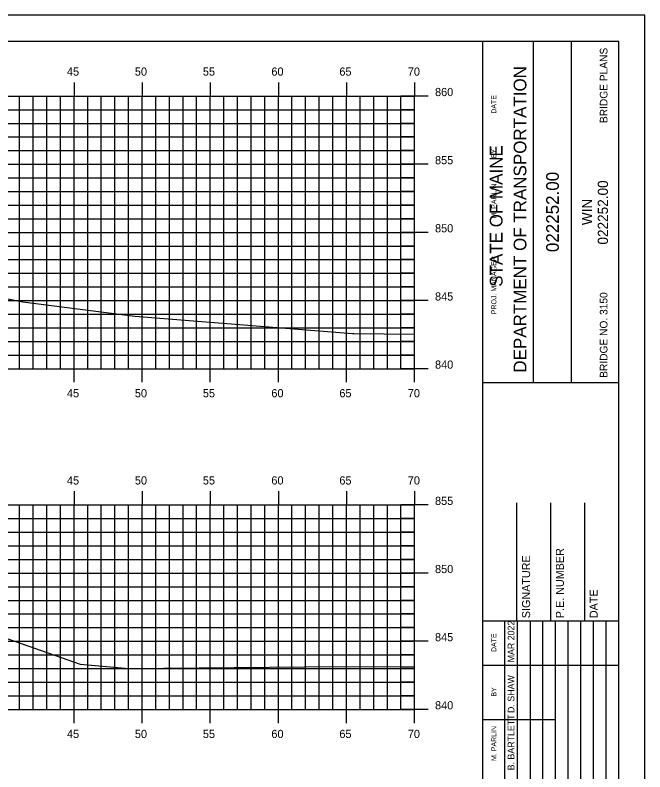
# Model space of a CAD drawing. Extents: x 2194502 to 2194968, y 863888 to 863998.
# Drawn here: x 2194739.2 to 2194785.4, y 863942.9 to 863998.4 of the extents above; entities that cross this region are included whole.
import ezdxf

# ---------------------------------------------------------------- set-up
doc = ezdxf.new("R2010")
doc.units = 0
for name, color, linetype in [('BORDER', 7, 'Continuous'), ('BRIDGE_TITLE', 7, 'Continuous'), ('H_V ANNOTATION', 7, 'Continuous'), ('MAJOR', 7, 'Continuous'), ('MINOR', 7, 'Continuous'), ('PLOT BOUNDARY', 7, 'Continuous'), ('S_Roadway_Centerline', 7, 'Continuous')]:
    doc.layers.add(name, color=color, linetype=linetype)

msp = doc.modelspace()

# ---------------------------------------------------------------- linework, layer by layer
at = {"layer": 'BORDER'}
for p, q in [((2194773.499, 863891.446), (2194773.499, 863996.446)), ((2194777.228, 863971.443), (2194777.228, 863996.443)), ((2194780.023, 863971.443), (2194780.023, 863996.443)), ((2194773.5, 863971.44), (2194783.499, 863971.44)), ((2194775.999, 863953.949), (2194775.999, 863962.596)), ((2194778.499, 863953.949), (2194778.499, 863962.596)), ((2194780.999, 863953.949), (2194780.999, 863962.596)), ((2194773.499, 863953.949), (2194783.499, 863953.949))]:
    msp.add_line(p, q, dxfattribs=at)
msp.add_lwpolyline([(2194623.499, 863891.446), (2194783.499, 863891.446), (2194783.499, 863996.446), (2194623.499, 863996.446)], close=True, dxfattribs=at)
for points in [[(2194775.114, 863950.699), (2194775.114, 863953.949)], [(2194776.047, 863936.452), (2194776.047, 863953.949)], [(2194776.979, 863953.949), (2194776.979, 863936.452)], [(2194777.91, 863936.452), (2194777.91, 863953.949)], [(2194778.842, 863936.452), (2194778.842, 863953.949)], [(2194779.774, 863936.452), (2194779.774, 863953.949)], [(2194780.705, 863936.452), (2194780.705, 863953.949)], [(2194781.637, 863936.452), (2194781.637, 863953.949)], [(2194782.569, 863936.452), (2194782.569, 863953.949)], [(2194775.115, 863936.452), (2194775.115, 863953.243)], [(2194773.499, 863950.699), (2194783.499, 863950.699)], [(2194773.499, 863946.699), (2194775.115, 863946.699)], [(2194775.114, 863946.699), (2194778.841, 863946.699)]]:
    msp.add_lwpolyline(points, dxfattribs=at)
at = {"layer": 'MAJOR'}
for p, q in [((2194743.499, 863993.448), (2194743.499, 863992.446)), ((2194748.499, 863993.448), (2194748.499, 863992.446)), ((2194753.499, 863993.448), (2194753.499, 863992.446)), ((2194758.499, 863993.448), (2194758.499, 863992.446)), ((2194763.499, 863993.448), (2194763.499, 863992.446)), ((2194768.499, 863993.448), (2194768.499, 863992.446)), ((2194628.499, 863992.446), (2194768.499, 863992.446)), ((2194628.499, 863992.446), (2194768.499, 863992.446)), ((2194743.499, 863972.446), (2194743.499, 863992.446)), ((2194748.499, 863972.446), (2194748.499, 863992.446)), ((2194753.499, 863972.446), (2194753.499, 863992.446)), ((2194758.499, 863972.446), (2194758.499, 863992.446)), ((2194763.499, 863972.446), (2194763.499, 863992.446)), ((2194769.501, 863992.446), (2194767.497, 863992.446)), ((2194768.499, 863972.446), (2194768.499, 863992.446)), ((2194768.499, 863972.446), (2194768.499, 863992.446)), ((2194628.499, 863987.446), (2194768.499, 863987.446)), ((2194769.501, 863987.446), (2194767.497, 863987.446)), ((2194628.499, 863982.446), (2194768.499, 863982.446)), ((2194769.501, 863982.446), (2194767.497, 863982.446)), ((2194628.499, 863977.446), (2194768.499, 863977.446)), ((2194769.501, 863977.446), (2194767.497, 863977.446)), ((2194628.499, 863972.446), (2194768.499, 863972.446)), ((2194743.499, 863971.444), (2194743.499, 863972.446)), ((2194748.499, 863971.444), (2194748.499, 863972.446)), ((2194753.499, 863971.444), (2194753.499, 863972.446)), ((2194758.499, 863971.444), (2194758.499, 863972.446)), ((2194763.499, 863971.444), (2194763.499, 863972.446)), ((2194769.501, 863972.446), (2194767.497, 863972.446)), ((2194768.499, 863971.444), (2194768.499, 863972.446)), ((2194743.499, 863963.448), (2194743.499, 863962.446)), ((2194748.499, 863963.448), (2194748.499, 863962.446)), ((2194753.499, 863963.448), (2194753.499, 863962.446)), ((2194758.499, 863963.448), (2194758.499, 863962.446)), ((2194763.499, 863963.448), (2194763.499, 863962.446)), ((2194768.499, 863963.448), (2194768.499, 863962.446)), ((2194628.499, 863962.446), (2194768.499, 863962.446)), ((2194743.499, 863947.446), (2194743.499, 863962.446)), ((2194748.499, 863947.446), (2194748.499, 863962.446)), ((2194753.499, 863947.446), (2194753.499, 863962.446)), ((2194758.499, 863947.446), (2194758.499, 863962.446)), ((2194763.499, 863947.446), (2194763.499, 863962.446)), ((2194769.501, 863962.446), (2194767.497, 863962.446)), ((2194768.499, 863947.446), (2194768.499, 863962.446)), ((2194768.499, 863947.446), (2194768.499, 863962.446)), ((2194628.499, 863957.446), (2194768.499, 863957.446)), ((2194769.501, 863957.446), (2194767.497, 863957.446)), ((2194628.499, 863952.446), (2194768.499, 863952.446)), ((2194769.501, 863952.446), (2194767.497, 863952.446)), ((2194628.499, 863947.446), (2194768.499, 863947.446)), ((2194743.499, 863946.444), (2194743.499, 863947.446)), ((2194748.499, 863946.444), (2194748.499, 863947.446)), ((2194753.499, 863946.444), (2194753.499, 863947.446)), ((2194758.499, 863946.444), (2194758.499, 863947.446)), ((2194763.499, 863946.444), (2194763.499, 863947.446)), ((2194769.501, 863947.446), (2194767.497, 863947.446)), ((2194768.499, 863946.444), (2194768.499, 863947.446))]:
    msp.add_line(p, q, dxfattribs=at)
at = {"layer": 'MINOR'}
for p, q in [((2194739.499, 863972.446), (2194739.499, 863992.446)), ((2194740.499, 863972.446), (2194740.499, 863992.446)), ((2194741.499, 863972.446), (2194741.499, 863992.446)), ((2194742.499, 863972.446), (2194742.499, 863992.446)), ((2194744.499, 863972.446), (2194744.499, 863992.446)), ((2194745.499, 863972.446), (2194745.499, 863992.446)), ((2194746.499, 863972.446), (2194746.499, 863992.446)), ((2194747.499, 863972.446), (2194747.499, 863992.446)), ((2194749.499, 863972.446), (2194749.499, 863992.446)), ((2194750.499, 863972.446), (2194750.499, 863992.446)), ((2194751.499, 863972.446), (2194751.499, 863992.446)), ((2194752.499, 863972.446), (2194752.499, 863992.446)), ((2194754.499, 863972.446), (2194754.499, 863992.446)), ((2194755.499, 863972.446), (2194755.499, 863992.446)), ((2194756.499, 863972.446), (2194756.499, 863992.446)), ((2194757.499, 863972.446), (2194757.499, 863992.446)), ((2194759.499, 863972.446), (2194759.499, 863992.446)), ((2194760.499, 863972.446), (2194760.499, 863992.446)), ((2194761.499, 863972.446), (2194761.499, 863992.446)), ((2194762.499, 863972.446), (2194762.499, 863992.446)), ((2194764.499, 863972.446), (2194764.499, 863992.446)), ((2194765.499, 863972.446), (2194765.499, 863992.446)), ((2194766.499, 863972.446), (2194766.499, 863992.446)), ((2194767.499, 863972.446), (2194767.499, 863992.446)), ((2194628.499, 863991.446), (2194768.499, 863991.446)), ((2194768.499, 863991.446), (2194767.497, 863991.446)), ((2194628.499, 863990.446), (2194768.499, 863990.446)), ((2194768.499, 863990.446), (2194767.497, 863990.446)), ((2194628.499, 863989.446), (2194768.499, 863989.446)), ((2194768.499, 863989.446), (2194767.497, 863989.446)), ((2194628.499, 863988.446), (2194768.499, 863988.446)), ((2194768.499, 863988.446), (2194767.497, 863988.446)), ((2194628.499, 863986.446), (2194768.499, 863986.446)), ((2194768.499, 863986.446), (2194767.497, 863986.446)), ((2194628.499, 863985.446), (2194768.499, 863985.446)), ((2194768.499, 863985.446), (2194767.497, 863985.446)), ((2194628.499, 863984.446), (2194768.499, 863984.446)), ((2194768.499, 863984.446), (2194767.497, 863984.446)), ((2194628.499, 863983.446), (2194768.499, 863983.446)), ((2194768.499, 863983.446), (2194767.497, 863983.446)), ((2194628.499, 863981.446), (2194768.499, 863981.446)), ((2194768.499, 863981.446), (2194767.497, 863981.446)), ((2194628.499, 863980.446), (2194768.499, 863980.446)), ((2194768.499, 863980.446), (2194767.497, 863980.446)), ((2194628.499, 863979.446), (2194768.499, 863979.446)), ((2194768.499, 863979.446), (2194767.497, 863979.446)), ((2194628.499, 863978.446), (2194768.499, 863978.446)), ((2194768.499, 863978.446), (2194767.497, 863978.446)), ((2194628.499, 863976.446), (2194768.499, 863976.446)), ((2194768.499, 863976.446), (2194767.497, 863976.446)), ((2194628.499, 863975.446), (2194768.499, 863975.446)), ((2194768.499, 863975.446), (2194767.497, 863975.446)), ((2194628.499, 863974.446), (2194768.499, 863974.446)), ((2194768.499, 863974.446), (2194767.497, 863974.446)), ((2194628.499, 863973.446), (2194768.499, 863973.446)), ((2194768.499, 863973.446), (2194767.497, 863973.446)), ((2194739.499, 863947.446), (2194739.499, 863962.446)), ((2194740.499, 863947.446), (2194740.499, 863962.446)), ((2194741.499, 863947.446), (2194741.499, 863962.446)), ((2194742.499, 863947.446), (2194742.499, 863962.446)), ((2194744.499, 863947.446), (2194744.499, 863962.446)), ((2194745.499, 863947.446), (2194745.499, 863962.446)), ((2194746.499, 863947.446), (2194746.499, 863962.446)), ((2194747.499, 863947.446), (2194747.499, 863962.446)), ((2194749.499, 863947.446), (2194749.499, 863962.446)), ((2194750.499, 863947.446), (2194750.499, 863962.446)), ((2194751.499, 863947.446), (2194751.499, 863962.446)), ((2194752.499, 863947.446), (2194752.499, 863962.446)), ((2194754.499, 863947.446), (2194754.499, 863962.446)), ((2194755.499, 863947.446), (2194755.499, 863962.446)), ((2194756.499, 863947.446), (2194756.499, 863962.446)), ((2194757.499, 863947.446), (2194757.499, 863962.446)), ((2194759.499, 863947.446), (2194759.499, 863962.446)), ((2194760.499, 863947.446), (2194760.499, 863962.446)), ((2194761.499, 863947.446), (2194761.499, 863962.446)), ((2194762.499, 863947.446), (2194762.499, 863962.446)), ((2194764.499, 863947.446), (2194764.499, 863962.446)), ((2194765.499, 863947.446), (2194765.499, 863962.446)), ((2194766.499, 863947.446), (2194766.499, 863962.446)), ((2194767.499, 863947.446), (2194767.499, 863962.446)), ((2194628.499, 863961.446), (2194768.499, 863961.446)), ((2194768.499, 863961.446), (2194767.497, 863961.446)), ((2194628.499, 863960.446), (2194768.499, 863960.446)), ((2194768.499, 863960.446), (2194767.497, 863960.446)), ((2194628.499, 863959.446), (2194768.499, 863959.446)), ((2194768.499, 863959.446), (2194767.497, 863959.446)), ((2194628.499, 863958.446), (2194768.499, 863958.446)), ((2194768.499, 863958.446), (2194767.497, 863958.446)), ((2194628.499, 863956.446), (2194768.499, 863956.446)), ((2194768.499, 863956.446), (2194767.497, 863956.446)), ((2194628.499, 863955.446), (2194768.499, 863955.446)), ((2194768.499, 863955.446), (2194767.497, 863955.446)), ((2194628.499, 863954.446), (2194768.499, 863954.446)), ((2194768.499, 863954.446), (2194767.497, 863954.446)), ((2194628.499, 863953.446), (2194768.499, 863953.446)), ((2194768.499, 863953.446), (2194767.497, 863953.446)), ((2194628.499, 863951.446), (2194768.499, 863951.446)), ((2194768.499, 863951.446), (2194767.497, 863951.446)), ((2194628.499, 863950.446), (2194768.499, 863950.446)), ((2194768.499, 863950.446), (2194767.497, 863950.446)), ((2194628.499, 863949.446), (2194768.499, 863949.446)), ((2194768.499, 863949.446), (2194767.497, 863949.446)), ((2194628.499, 863948.446), (2194768.499, 863948.446)), ((2194768.499, 863948.446), (2194767.497, 863948.446))]:
    msp.add_line(p, q, dxfattribs=at)
at = {"layer": 'PLOT BOUNDARY'}
msp.add_lwpolyline([(2194615.406, 863888.387), (2194785.406, 863888.387), (2194785.406, 863998.387), (2194615.406, 863998.387)], close=True, dxfattribs=at)
at = {"layer": 'S_Roadway_Centerline'}
for points in [[(2194666, 863982.427), (2194673.123, 863983.818), (2194674.81, 863984.278), (2194676.501, 863984.313), (2194683.393, 863984.628), (2194686.919, 863984.805), (2194687.224, 863984.838), (2194697.976, 863984.99), (2194698.502, 863984.991), (2194709.585, 863984.836), (2194710.081, 863984.824), (2194710.192, 863984.815), (2194712.436, 863984.681), (2194712.596, 863984.644), (2194714.834, 863984.124), (2194714.836, 863984.114), (2194716.134, 863983.876), (2194717.012, 863983.443), (2194731.656, 863978.954), (2194739.75, 863977.349), (2194747.963, 863976.289), (2194763.932, 863975.023), (2194764.031, 863975.023), (2194768.499, 863974.976)], [(2194670.976, 863957.344), (2194680.42, 863958.572), (2194680.878, 863958.638), (2194680.949, 863958.642), (2194685.157, 863958.786), (2194687.193, 863959.008), (2194692.54, 863959.083), (2194698.501, 863959.102), (2194704.085, 863959.024), (2194710.13, 863958.869), (2194711.477, 863958.767), (2194712.598, 863958.699), (2194714.403, 863958.284), (2194715.073, 863958.128), (2194715.095, 863958.006), (2194727.745, 863955.685), (2194729.344, 863955.492), (2194730.418, 863955.285), (2194733.533, 863954.397), (2194743.953, 863950.759), (2194747.523, 863950.45), (2194760.422, 863950.562), (2194768.499, 863950.601)]]:
    msp.add_lwpolyline(points, dxfattribs=at)

# ---------------------------------------------------------------- texts
at = {"layer": 'BORDER'}
for s, height, p in [('DEPARTMENT OF TRANSPORTATION', 0.93176, (2194776.706, 863972.152)), ('DATE', 0.3714, (2194774.504, 863991.154)), ('STATE OF MAINE', 0.93176, (2194774.955, 863978.458)), ('BY', 0.3714, (2194774.504, 863987.884)), ('022252.00', 0.9318, (2194779.091, 863980.999)), ('022252.00', 0.7453, (2194782.695, 863981.551)), ('M. PARLIN', 0.3727, (2194774.504, 863983.462)), ('WIN', 0.7453, (2194781.536, 863982.976)), ('PROJ. MANAGER', 0.37275, (2194774.504, 863976.437)), ('P.E. NUMBER', 0.59055, (2194779.46, 863954.141)), ('SIGNATURE', 0.5906, (2194776.98, 863954.141)), ('DATE', 0.5906, (2194781.941, 863954.141)), ('MAR 2022', 0.4845, (2194775.822, 863950.897)), ('DATE', 0.3714, (2194774.504, 863951.654)), ('D. SHAW', 0.4845, (2194775.822, 863947.184)), ('BY', 0.3714, (2194774.504, 863948.384)), ('B. BARTLETT', 0.48455, (2194775.822, 863942.972)), ('M. PARLIN', 0.3727, (2194774.504, 863943.656))]:
    msp.add_text(s, height=height, rotation=90, dxfattribs=at).set_placement(p)
at = {"layer": 'BRIDGE_TITLE'}
for s, p in [('BRIDGE PLANS', (2194782.658, 863990.47)), ('BRIDGE NO. 3150', (2194782.658, 863971.776))]:
    msp.add_text(s, height=0.55901, rotation=90, dxfattribs=at).set_placement(p)
at = {"layer": 'H_V ANNOTATION'}
for s, p in [('45', (2194742.977, 863993.946)), ('50', (2194747.964, 863993.946)), ('55', (2194752.956, 863993.946)), ('60', (2194757.985, 863993.946)), ('65', (2194762.977, 863993.946)), ('70', (2194768.001, 863993.946)), ('860', (2194769.999, 863992.446)), ('855', (2194769.999, 863987.446)), ('850', (2194769.999, 863982.446)), ('845', (2194769.999, 863977.446)), ('840', (2194769.999, 863972.446)), ('45', (2194742.977, 863970.346)), ('50', (2194747.964, 863970.346)), ('55', (2194752.956, 863970.346)), ('60', (2194757.985, 863970.346)), ('65', (2194762.977, 863970.346)), ('70', (2194768.001, 863970.346)), ('45', (2194742.977, 863963.946)), ('50', (2194747.964, 863963.946)), ('55', (2194752.956, 863963.946)), ('60', (2194757.985, 863963.946)), ('65', (2194762.977, 863963.946)), ('70', (2194768.001, 863963.946)), ('855', (2194769.999, 863962.446)), ('850', (2194769.999, 863957.446)), ('845', (2194769.999, 863952.446)), ('840', (2194769.999, 863947.446)), ('45', (2194742.977, 863945.346)), ('50', (2194747.964, 863945.346)), ('55', (2194752.956, 863945.346)), ('60', (2194757.985, 863945.346)), ('65', (2194762.977, 863945.346)), ('70', (2194768.001, 863945.346))]:
    msp.add_text(s, height=0.6, dxfattribs=at).set_placement(p)

doc.saveas('drawing.dxf')
